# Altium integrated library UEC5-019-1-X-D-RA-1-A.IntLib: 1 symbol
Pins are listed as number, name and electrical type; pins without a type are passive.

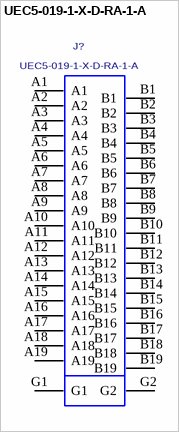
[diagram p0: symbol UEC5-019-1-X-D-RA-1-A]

## UEC5-019-1-X-D-RA-1-A
designator J?
0.5MM EDGE RATE SOCKET ASSEMBLY.; MANUFACTURER: SAMTEC
footprint UEC5-019-1-X-D-RA-1-A
pins: A1, A2, A3, A4, A5, A6, A7, A8, A9, A10, A11, A12, A13, A14, A15, A16, A17, A18, A19, B1, B2, B3, B4, B5, B6, B7, B8, B9, B10, B11, B12, B13, B14, B15, B16, B17, B18, B19, G1, G2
